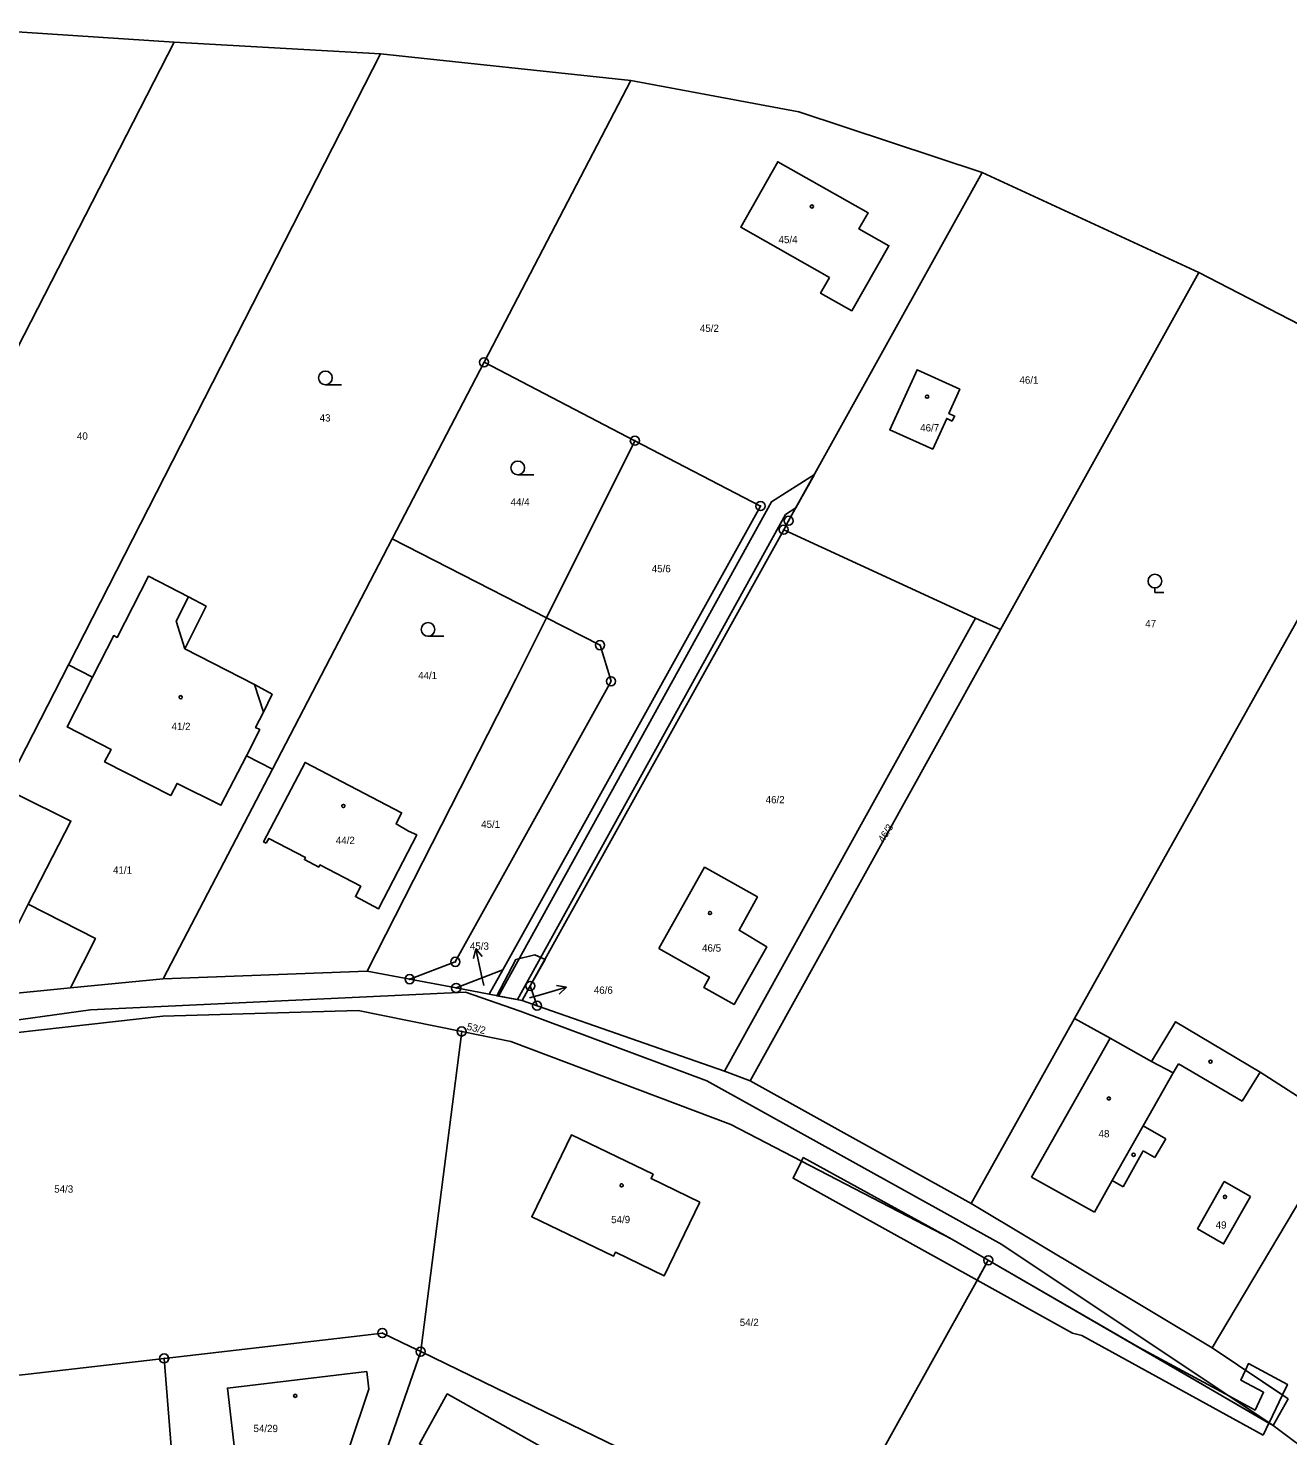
# Model space of a CAD drawing. Extents: x -587171 to -555306, y -1167727 to -1074732.
# Drawn here: x -559489.7 to -559351, y -1076445.1 to -1076290.1 of the extents above; entities that cross this region are included whole.
import ezdxf

# ---------------------------------------------------------------- set-up
doc = ezdxf.new("R2010")
doc.units = 0
for name, color, linetype in [('Hranice parcel', 7, 'Continuous'), ('Parcelní čísla', 7, 'Continuous'), ('Pop  PČ popisy', 7, 'Continuous'), ('Vnitřní kresba', 7, 'Continuous'), ('Věcná břemena k části', 7, 'Continuous'), ('Značky bodu BP', 7, 'Continuous'), ('Značky budov', 7, 'Continuous'), ('Značky kultur', 7, 'Continuous')]:
    doc.layers.add(name, color=color, linetype=linetype)

msp = doc.modelspace()

# ---------------------------------------------------------------- linework, layer by layer
at = {"layer": 'Hranice parcel'}
for p, q in [((-559497.1, -1076290.11), (-559473.66, -1076291.66)), ((-559473.66, -1076291.66), (-559501.48, -1076345.93)), ((-559485.29, -1076360.22), (-559450.92, -1076292.94)), ((-559450.92, -1076292.94), (-559473.66, -1076291.66)), ((-559423.37, -1076295.86), (-559450.92, -1076292.94)), ((-559439.53, -1076326.91), (-559423.37, -1076295.86)), ((-559360.86, -1076317.01), (-559384.7, -1076305.99)), ((-559382.67, -1076356.34), (-559360.86, -1076317.01)), ((-559335.84, -1076329.97), (-559360.86, -1076317.01)), ((-559449.65, -1076346.36), (-559439.53, -1076326.91)), ((-559439.53, -1076326.91), (-559422.93, -1076335.55)), ((-559374.52, -1076399.19), (-559335.84, -1076329.97)), ((-559432.65, -1076355.05), (-559422.93, -1076335.55)), ((-559434.45, -1076395.58), (-559406.54, -1076345.35)), ((-559406.54, -1076345.35), (-559385.42, -1076355.09)), ((-559462.83, -1076371.7), (-559449.65, -1076346.36)), ((-559432.65, -1076355.05), (-559449.65, -1076346.36)), ((-559432.65, -1076355.05), (-559436.02, -1076361.81)), ((-559426.76, -1076358.06), (-559432.65, -1076355.05)), ((-559413.05, -1076404.98), (-559385.42, -1076355.09)), ((-559410.23, -1076406.03), (-559382.67, -1076356.34)), ((-559385.42, -1076355.09), (-559382.67, -1076356.34)), ((-559492.25, -1076373.84), (-559485.29, -1076360.22)), ((-559485.29, -1076360.22), (-559482.63, -1076361.58)), ((-559436.02, -1076361.81), (-559452.4, -1076393.96)), ((-559465.7, -1076370.23), (-559462.83, -1076371.7)), ((-559462.83, -1076371.7), (-559474.85, -1076394.79)), ((-559485.06, -1076395.8), (-559474.85, -1076394.79)), ((-559474.85, -1076394.79), (-559452.4, -1076393.96)), ((-559447.72, -1076394.84), (-559452.4, -1076393.96)), ((-559442.6, -1076395.81), (-559447.72, -1076394.84)), ((-559437.47, -1076393.81), (-559442.6, -1076395.81)), ((-559437.47, -1076393.81), (-559438.96, -1076396.5)), ((-559504.45, -1076397.71), (-559485.06, -1076395.8)), ((-559442.6, -1076395.81), (-559438.96, -1076396.5)), ((-559438.96, -1076396.5), (-559435.34, -1076397.19)), ((-559435.34, -1076397.19), (-559434.45, -1076395.58)), ((-559434.45, -1076395.58), (-559433.69, -1076397.77)), ((-559435.34, -1076397.19), (-559433.69, -1076397.77)), ((-559433.69, -1076397.77), (-559413.05, -1076404.98)), ((-559385.89, -1076419.53), (-559374.52, -1076399.19)), ((-559413.05, -1076404.98), (-559410.23, -1076406.03)), ((-559410.23, -1076406.03), (-559385.89, -1076419.53)), ((-559359.39, -1076435.43), (-559344.86, -1076411.02)), ((-559385.89, -1076419.53), (-559359.39, -1076435.43)), ((-559352.65, -1076443.99), (-559384.02, -1076425.8)), ((-559359.39, -1076435.43), (-559351, -1076441.05)), ((-559472.55, -1076463.7), (-559474.75, -1076436.61)), ((-559456.26, -1076463.98), (-559446.5, -1076435.86)), ((-559351, -1076441.05), (-559352.65, -1076443.99)), ((-559342.79, -1076451.39), (-559352.65, -1076443.99))]:
    msp.add_line(p, q, dxfattribs=at)
for points in [[(-559384.7, -1076305.99), (-559404.88, -1076299.33), (-559423.37, -1076295.86)], [(-559401.51, -1076317.56), (-559411.27, -1076312.04), (-559407.2, -1076304.83), (-559397.26, -1076310.44), (-559398.26, -1076312.21), (-559394.97, -1076314.08), (-559399.03, -1076321.24), (-559402.48, -1076319.3), (-559401.51, -1076317.56)], [(-559406.54, -1076345.35), (-559406, -1076344.36), (-559384.7, -1076305.99)], [(-559387.98, -1076333.38), (-559388.6, -1076333.09), (-559390.13, -1076336.47), (-559394.87, -1076334.33), (-559391.86, -1076327.73), (-559387.16, -1076329.87), (-559388.36, -1076332.55), (-559387.73, -1076332.83), (-559387.98, -1076333.38)], [(-559422.93, -1076335.55), (-559409.1, -1076342.74), (-559437.47, -1076393.81)], [(-559482.63, -1076361.58), (-559480.3, -1076357), (-559479.91, -1076357.2), (-559476.48, -1076350.46), (-559472.06, -1076352.72), (-559470.13, -1076353.75), (-559472.47, -1076358.46), (-559464.79, -1076362.39), (-559462.87, -1076363.46), (-559463.82, -1076365.44), (-559464.68, -1076367.13), (-559464.23, -1076367.35), (-559465.7, -1076370.23)], [(-559447.72, -1076394.84), (-559442.7, -1076392.93), (-559425.55, -1076362.04), (-559426.76, -1076358.06)], [(-559465.7, -1076370.23), (-559468.5, -1076375.68), (-559473.32, -1076373.28), (-559474.02, -1076374.61), (-559481.3, -1076370.89), (-559480.6, -1076369.53), (-559485.42, -1076367.06), (-559482.63, -1076361.58)], [(-559463.52, -1076379.86), (-559463.8, -1076379.72), (-559459.23, -1076370.97), (-559448.61, -1076376.51), (-559449.22, -1076377.74), (-559447.84, -1076378.53), (-559446.95, -1076378.95), (-559447.91, -1076380.86), (-559451.16, -1076387.1), (-559453.69, -1076385.74), (-559453.11, -1076384.6), (-559457.61, -1076382.26), (-559457.73, -1076382.49), (-559459.31, -1076381.68), (-559459.2, -1076381.43), (-559463.22, -1076379.34), (-559463.52, -1076379.86)], [(-559489.71, -1076386.58), (-559490.94, -1076388.99), (-559496.72, -1076386.07), (-559490.85, -1076374.55)], [(-559490.85, -1076374.55), (-559485.02, -1076377.43), (-559489.71, -1076386.58)], [(-559420.28, -1076391.46), (-559415.25, -1076382.52), (-559409.44, -1076385.79), (-559411.46, -1076389.45), (-559408.41, -1076391.29), (-559412, -1076397.63), (-559415.35, -1076395.75), (-559414.72, -1076394.61), (-559420.28, -1076391.46)], [(-559485.06, -1076395.8), (-559482.32, -1076390.35), (-559489.71, -1076386.58)], [(-559529.43, -1076404.66), (-559482.86, -1076398.2), (-559441.57, -1076396.27), (-559435.57, -1076398.37), (-559414.99, -1076406.03), (-559382.52, -1076424.05), (-559352.65, -1076443.99)], [(-559441.99, -1076400.6), (-559453.4, -1076398.3), (-559474.91, -1076398.9), (-559504.91, -1076402.3), (-559529.43, -1076404.66)], [(-559344.86, -1076411.02), (-559354.09, -1076405.07), (-559363.41, -1076399.53), (-559366.07, -1076403.89), (-559370.59, -1076401.33), (-559374.52, -1076399.19)], [(-559441.99, -1076400.6), (-559446.45, -1076435.47), (-559446.5, -1076435.86)], [(-559384.02, -1076425.8), (-559388.04, -1076423.47), (-559412.35, -1076410.85), (-559436.57, -1076401.7), (-559441.99, -1076400.6)], [(-559415.77, -1076419.38), (-559419.7, -1076427.51), (-559425.07, -1076424.91), (-559425.29, -1076425.36), (-559434.28, -1076421.01), (-559429.91, -1076411.99), (-559420.92, -1076416.32), (-559421.14, -1076416.78), (-559415.77, -1076419.38)], [(-559355.14, -1076418.79), (-559358.12, -1076423.99), (-559360.98, -1076422.33), (-559358.05, -1076417.14), (-559355.14, -1076418.79)], [(-559402.27, -1076458.62), (-559385, -1076427.56), (-559384.02, -1076425.8)], [(-559474.75, -1076436.61), (-559454.8, -1076434.3), (-559450.73, -1076433.81), (-559447.66, -1076435.3), (-559446.5, -1076435.86)], [(-559497.59, -1076439.56), (-559493.12, -1076438.72), (-559489.72, -1076438.34), (-559474.75, -1076436.61)], [(-559446.5, -1076435.86), (-559428.63, -1076444.54), (-559421.29, -1076448.1), (-559420.61, -1076448.48)], [(-559452.2, -1076440.01), (-559454.35, -1076446.33), (-559466.85, -1076447.81), (-559467.79, -1076439.88), (-559452.45, -1076438.06), (-559452.2, -1076440.01)], [(-559436.77, -1076452.93), (-559435.46, -1076453.68), (-559438.52, -1076459.15), (-559440.97, -1076457.81), (-559441.66, -1076459.12), (-559446.73, -1076456.27), (-559443.19, -1076449.97), (-559444.47, -1076449.26), (-559443.6, -1076447.7), (-559446.64, -1076446), (-559443.59, -1076440.51), (-559433.1, -1076446.41), (-559436.77, -1076452.93)]]:
    msp.add_lwpolyline(points, dxfattribs=at)
at = {"layer": 'Pop  PČ popisy'}
for p, q in [((-559440.42, -1076391.49), (-559440.71, -1076392.57)), ((-559439.8, -1076394.42), (-559440.42, -1076391.49)), ((-559440.42, -1076391.49), (-559439.73, -1076392.36)), ((-559439.57, -1076395.52), (-559439.8, -1076394.42)), ((-559434.52, -1076396.9), (-559433.32, -1076396.55)), ((-559433.32, -1076396.55), (-559430.44, -1076395.72)), ((-559430.44, -1076395.72), (-559431.54, -1076395.52)), ((-559430.44, -1076395.72), (-559431.26, -1076396.48))]:
    msp.add_line(p, q, dxfattribs=at)
at = {"layer": 'Vnitřní kresba'}
for p, q in [((-559472.06, -1076352.72), (-559473.42, -1076355.4)), ((-559473.42, -1076355.4), (-559472.47, -1076358.46)), ((-559464.79, -1076362.39), (-559463.82, -1076365.44)), ((-559370.59, -1076401.33), (-559379.25, -1076416.66)), ((-559363.68, -1076405.15), (-559366.07, -1076403.89)), ((-559363.68, -1076405.15), (-559363.09, -1076404.16)), ((-559363.09, -1076404.16), (-559356.09, -1076408.26)), ((-559366.97, -1076410.99), (-559363.68, -1076405.15)), ((-559356.09, -1076408.26), (-559354.09, -1076405.07)), ((-559370.37, -1076417.03), (-559366.97, -1076410.99)), ((-559364.47, -1076412.41), (-559366.97, -1076410.99)), ((-559369.17, -1076417.71), (-559366.96, -1076413.76)), ((-559366.96, -1076413.76), (-559365.67, -1076414.47)), ((-559365.67, -1076414.47), (-559364.47, -1076412.41)), ((-559379.25, -1076416.66), (-559372.33, -1076420.51)), ((-559372.33, -1076420.51), (-559370.37, -1076417.03)), ((-559370.37, -1076417.03), (-559369.17, -1076417.71))]:
    msp.add_line(p, q, dxfattribs=at)
at = {"layer": 'Věcná břemena k části'}
for points in [[(-559437.93, -1076396.7), (-559435.86, -1076397.09), (-559406.36, -1076343.68), (-559405.21, -1076342.95), (-559403.17, -1076339.27), (-559407.87, -1076342.27)], [(-559438.12, -1076396.66), (-559435.34, -1076397.19), (-559434.45, -1076395.58), (-559432.82, -1076392.66), (-559433.93, -1076392.15), (-559436.04, -1076392.69)], [(-559385.24, -1076428), (-559384.02, -1076425.8), (-559388.04, -1076423.47), (-559404.58, -1076414.88), (-559405.51, -1076416.76)], [(-559404.39, -1076414.49), (-559404.58, -1076414.88), (-559388.04, -1076423.47)], [(-559353.75, -1076445.05), (-559353.12, -1076443.72), (-559367.42, -1076435.42), (-559384.02, -1076425.8), (-559385.24, -1076428), (-559374.75, -1076433.82), (-559373.73, -1076434.09)], [(-559367.42, -1076435.42), (-559353.12, -1076443.72), (-559353.1, -1076443.69), (-559357.47, -1076440.78)], [(-559351.64, -1076440.62), (-559351.09, -1076439.46), (-559355.38, -1076437.17), (-559355.71, -1076437.89)], [(-559357.47, -1076440.78), (-559353.1, -1076443.69), (-559351.64, -1076440.62), (-559355.71, -1076437.89), (-559356.22, -1076438.99), (-559353.72, -1076440.33), (-559354.65, -1076442.29)]]:
    msp.add_lwpolyline(points, close=True, dxfattribs=at)
at = {"layer": 'Značky bodu BP'}
for centre, radius in [((-559439.53, -1076326.91), 0.5), ((-559439.53, -1076326.91), 0.0303), ((-559422.93, -1076335.55), 0.5), ((-559422.93, -1076335.55), 0.0303), ((-559409.1, -1076342.74), 0.5), ((-559409.1, -1076342.74), 0.0303), ((-559406, -1076344.36), 0.5), ((-559406.54, -1076345.35), 0.5), ((-559406.54, -1076345.35), 0.0303), ((-559406, -1076344.36), 0.0303), ((-559426.76, -1076358.06), 0.5), ((-559426.76, -1076358.06), 0.0303), ((-559425.55, -1076362.04), 0.5), ((-559425.55, -1076362.04), 0.0303), ((-559442.7, -1076392.93), 0.5), ((-559442.7, -1076392.93), 0.0303), ((-559447.72, -1076394.84), 0.5), ((-559447.72, -1076394.84), 0.0303), ((-559442.6, -1076395.81), 0.5), ((-559434.45, -1076395.58), 0.5), ((-559442.6, -1076395.81), 0.0303), ((-559434.45, -1076395.58), 0.0303), ((-559433.69, -1076397.77), 0.5), ((-559433.69, -1076397.77), 0.0303), ((-559441.99, -1076400.6), 0.5), ((-559441.99, -1076400.6), 0.0303), ((-559384.02, -1076425.8), 0.5), ((-559384.02, -1076425.8), 0.0303), ((-559450.73, -1076433.81), 0.5), ((-559450.73, -1076433.81), 0.0303), ((-559446.5, -1076435.86), 0.5), ((-559474.75, -1076436.61), 0.5), ((-559474.75, -1076436.61), 0.0303), ((-559446.5, -1076435.86), 0.0303)]:
    msp.add_circle(centre, radius, dxfattribs=at)
at = {"layer": 'Značky budov'}
for centre in [(-559403.44, -1076309.75), (-559390.76, -1076330.7), (-559472.93, -1076363.79), (-559455.02, -1076375.77), (-559414.66, -1076387.56), (-559359.56, -1076403.92), (-559370.75, -1076407.98), (-559368.03, -1076414.18), (-559424.39, -1076417.55), (-559357.97, -1076418.82), (-559460.32, -1076440.73)]:
    msp.add_circle(centre, 0.175, dxfattribs=at)
at = {"layer": 'Značky kultur'}
for p, q in [((-559456.99, -1076329.38), (-559455.24, -1076329.38)), ((-559435.82, -1076339.29), (-559434.07, -1076339.29)), ((-559365.68, -1076351.75), (-559365.68, -1076352.25)), ((-559365.68, -1076352.25), (-559364.68, -1076352.25)), ((-559445.7, -1076357.08), (-559443.95, -1076357.08))]:
    msp.add_line(p, q, dxfattribs=at)
for centre in [(-559456.99, -1076328.63), (-559435.82, -1076338.54), (-559365.68, -1076351), (-559445.7, -1076356.33)]:
    msp.add_circle(centre, 0.75, dxfattribs=at)

# ---------------------------------------------------------------- texts
at = {"layer": 'Parcelní čísla'}
for s, p in [('45/4', (-559407.11, -1076313.79)), ('45/2', (-559415.77, -1076323.56)), ('46/1', (-559380.59, -1076329.26)), ('43', (-559457.63, -1076333.43)), ('40', (-559484.35, -1076335.43)), ('46/7', (-559391.52, -1076334.52)), ('44/4', (-559436.61, -1076342.7)), ('45/6', (-559421.07, -1076350.03)), ('47', (-559366.74, -1076356.09)), ('44/1', (-559446.79, -1076361.8)), ('41/2', (-559473.94, -1076367.41)), ('46/2', (-559408.53, -1076375.47)), ('45/1', (-559439.85, -1076378.18)), ('44/2', (-559455.85, -1076379.96)), ('41/1', (-559480.38, -1076383.23)), ('45/3', (-559441.09, -1076391.6)), ('46/5', (-559415.53, -1076391.81)), ('46/6', (-559427.45, -1076396.45)), ('48', (-559371.88, -1076412.26)), ('54/3', (-559486.85, -1076418.35)), ('54/9', (-559425.54, -1076421.71)), ('49', (-559358.99, -1076422.31)), ('54/2', (-559411.38, -1076433.04)), ('54/29', (-559464.91, -1076444.72))]:
    msp.add_text(s, height=0.803, dxfattribs=at).set_placement(p)
for s, rotation, p in [('46/3', 58, (-559395.55, -1076379.85)), ('53/2', 346, (-559441.49, -1076400.4))]:
    msp.add_text(s, height=0.803, rotation=rotation, dxfattribs=at).set_placement(p)

doc.saveas('drawing.dxf')
